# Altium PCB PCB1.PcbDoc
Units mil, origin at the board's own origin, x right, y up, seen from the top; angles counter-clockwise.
Board outline 1987 x 1197 mil, 2 copper layers (Top Layer, Bottom Layer); 31 components, 16 nets, 76 pads, 0 vias.
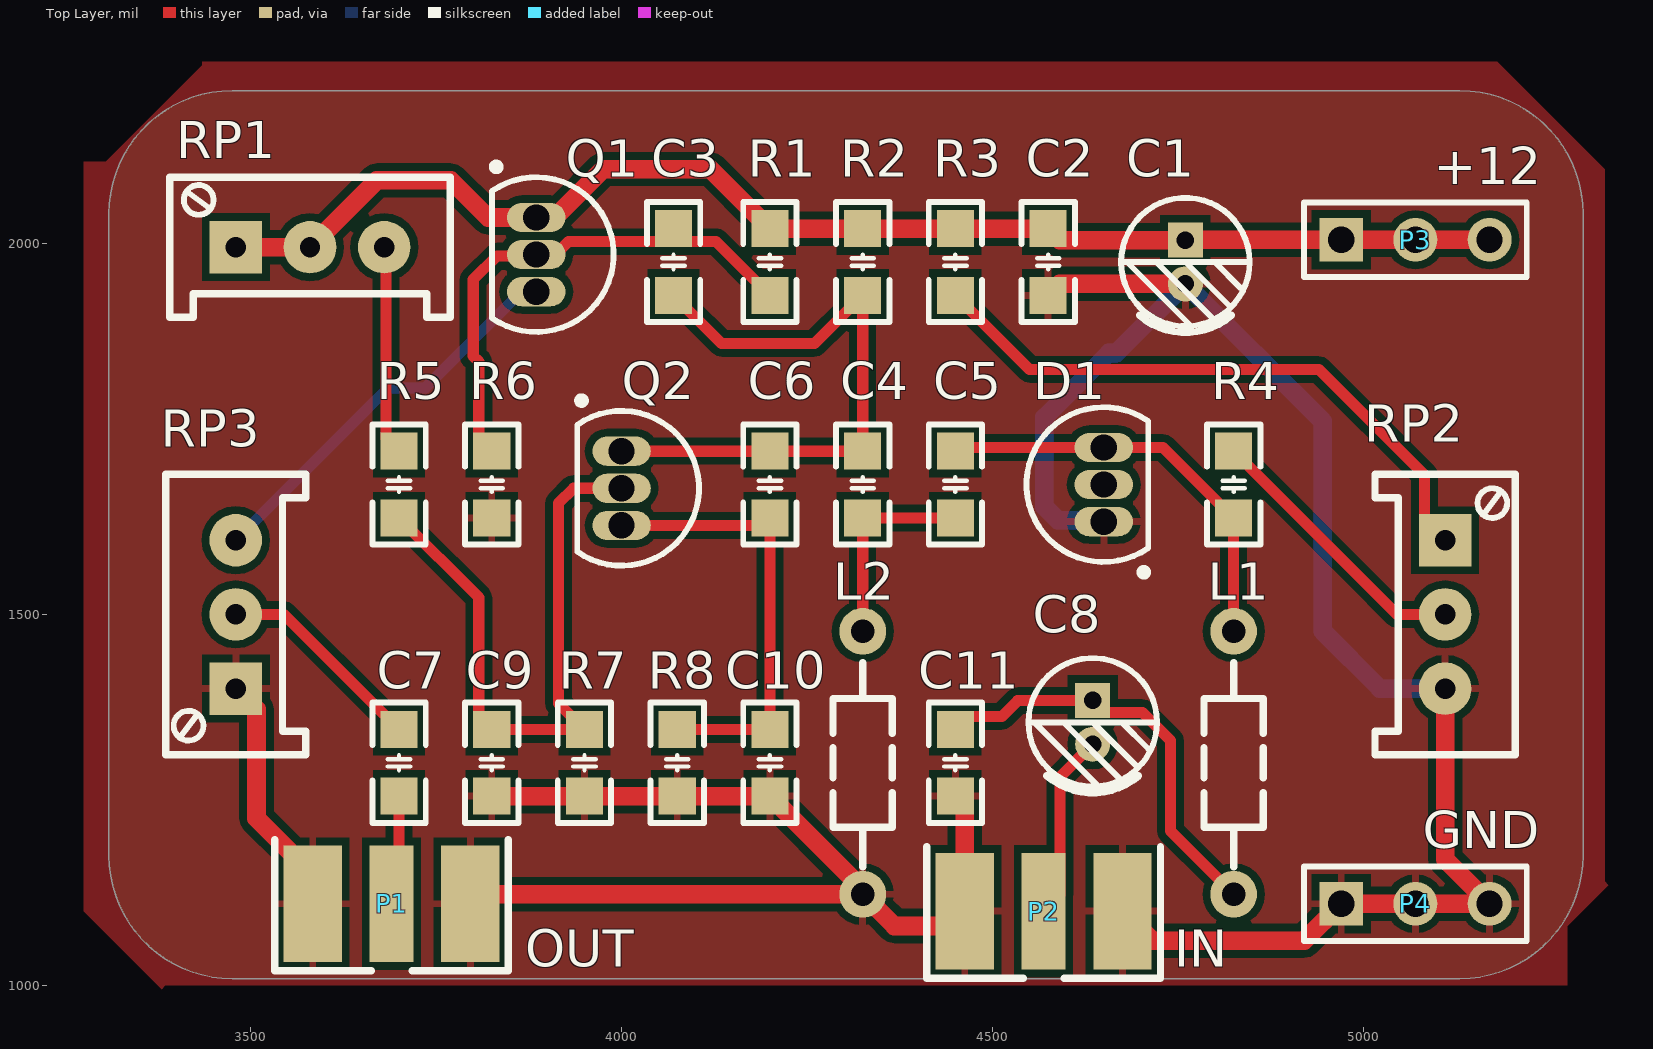
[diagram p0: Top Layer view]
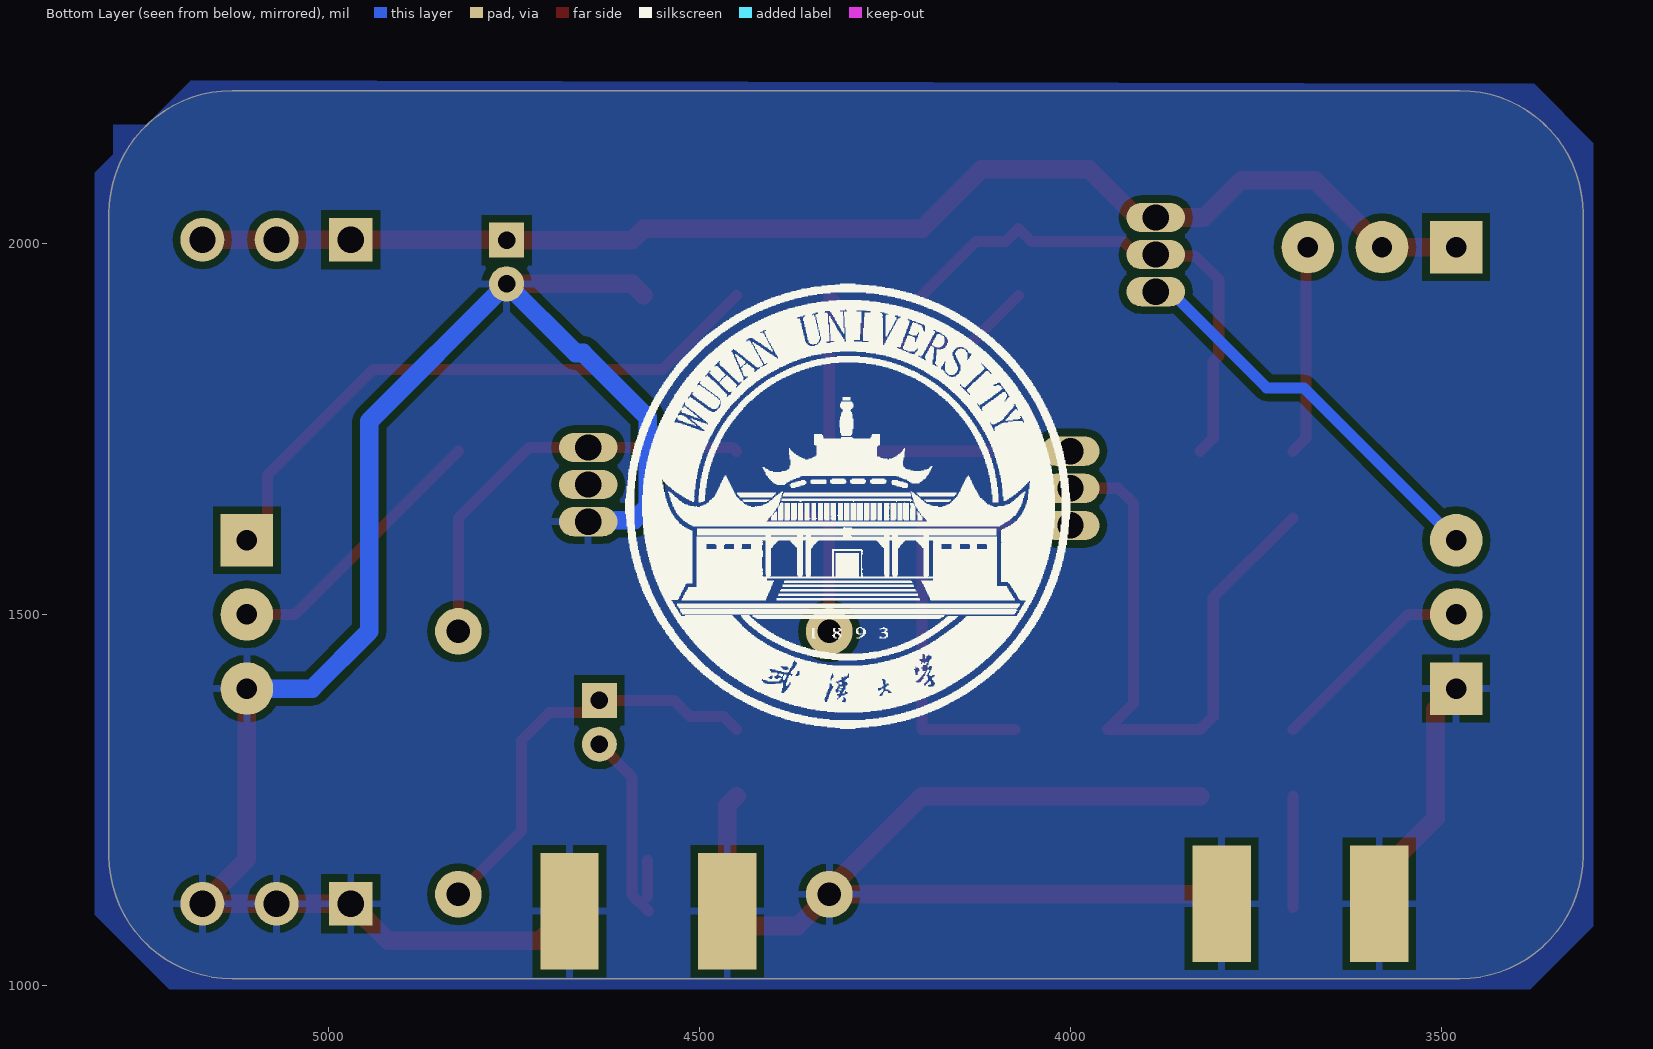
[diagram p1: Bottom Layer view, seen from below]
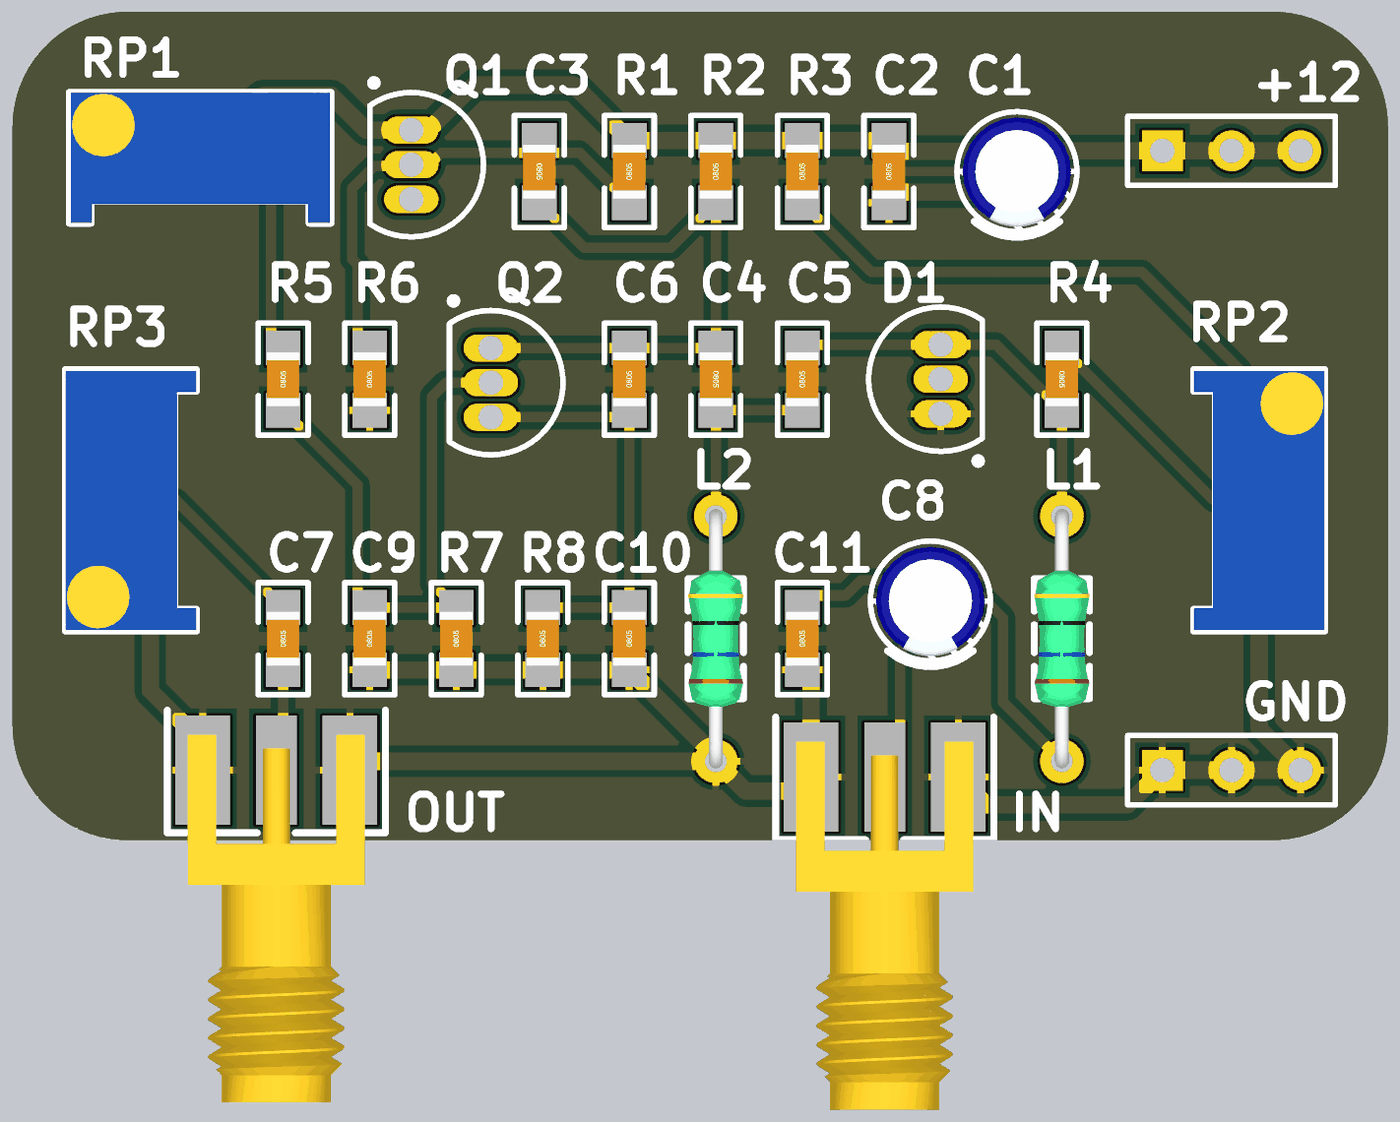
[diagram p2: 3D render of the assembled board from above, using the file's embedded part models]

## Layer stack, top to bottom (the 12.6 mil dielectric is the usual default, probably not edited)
Top Solder: solder mask 0.4, Solder Resist, Dk 3.5
Top Layer: signal copper 1.4
Dielectric 1: dielectric 12.6, FR-4, Dk 4.8
Bottom Layer: signal copper 1.4
Bottom Solder: solder mask 0.4, Solder Resist, Dk 3.5

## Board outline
3309,1175 ccw(c3475,1175) 3475,1009 5130,1009 ccw(c5130,1175) 5296,1175 5296,2040 ccw(c5130,2040) 5130,2206 3475,2206 ccw(c3475,2040) 3309,2040

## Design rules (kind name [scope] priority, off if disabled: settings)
Clearance [All] p1: gap=10 ignorepadtopadclearanceinfootprint=FALSE except(0: Arc-Hole Track-Hole SMDPad-Hole THPad-Hole Via-Hole Fill-Hole Poly-Hole Region-Hole Text-Hole; 1: Arc-Text Track-Text SMDPad-Text THPad-Text Via-Text Fill-Text Poly-Text Region-Text)
MinimumSolderMaskSliver [All] p1: minsoldermaskwidth=1
PolygonConnect [All] p1: connectstyle=Relief reliefconductorwidth=10 reliefentries=4 polygonreliefangle="90 Angle" airgapwidth=10
RoutingVias [All] p1: holewidth=28 width=50 viastyle="Through Hole" minholewidth=28 minwidth=50 maxholewidth=28 maxwidth=50
SilkToSilkClearance [All] p1: silktosilkclearance=1
SilkToSolderMaskClearance [IsPad] p1: minsilkscreentomaskgap=0 clearancetoexposedcopper=TRUE
SolderMaskExpansion [All] p1: expansion=4
Width [All] p1: maxlimit=50 minlimit=10 preferedwidth=15 minimp=50.000000 maximp=50.000000 favimp=50.000000
27 further rules are at their usual default settings.

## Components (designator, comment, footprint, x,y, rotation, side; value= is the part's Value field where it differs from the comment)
C1 "Cap Pol1" "CAP 1.5*4*8" 4760,1975 r270 top value=10uF
C2 "Cap" "C 0805_M" 4575,1975 r90 top value=10nF
C3 "Cap" "C 0805_M" 4070,1975 r270 top value=10pF
C4 "Cap" "C 0805_M" 4325,1675 r270 top value=51pF
C5 "Cap" "C 0805_M" 4450,1675 r90 top value=100nF
C6 "Cap" "C 0805_M" 4200,1675 r90 top value=300pF
C7 "Cap" "C 0805_M" 3700,1300 r90 top value=100pF
C8 "Cap Pol1" "CAP 1.5*4*8" 4635,1354.53 r270 top value=10uF
C9 "Cap" "C 0805_M" 3825,1300 r90 top value=10nF
C10 "Cap" "C 0805_M" 4200,1300 r90 top value=1nF
C11 "Cap" "C 0805_M" 4450,1300 r90 top value=1nF
D1 "BB910" TO-226-AA 4650,1675 r0 top
L1 "Inductor" AL0204 4825,1300 r90 top value=100uH
L2 "Inductor" AL0204 4325,1300 r90 top value=4.7uH
P1 "OUT" SMA-KE 3690,1110 r180 top
P2 "IN" SMA-KE 4568.9,1100 r180 top
P3 "+12" HDR1X3 4970,2005 r0 top
P4 "GND" HDR1X3 4970,1110 r0 top
Q1 "NPN" TO-226-AA 3885,1985 r180 top
Q2 "NPN" TO-226-AA 4000,1670 r180 top
R1 "Res1" "C 0805_M" 4200,1975 r90 top value=56K
R2 "Res1" "C 0805_M" 4325,1975 r90 top value=2K
R3 "Res1" "C 0805_M" 4450,1975 r90 top value=10K
R4 "Res1" "C 0805_M" 4825,1675 r270 top value=200K
R5 "Res1" "C 0805_M" 3700,1675 r90 top value=33K
R6 "Res1" "C 0805_M" 3825,1675 r90 top value=20K
R7 "Res1" "C 0805_M" 3950,1300 r90 top value=20K
R8 "Res1" "C 0805_M" 4075,1300 r90 top value=1K
RP1 "100K" 3296W 3580,1995 r0 top
RP2 "50K" 3296W 5110,1500 r270 top
RP3 "5K" 3296W 3480,1500 r90 top

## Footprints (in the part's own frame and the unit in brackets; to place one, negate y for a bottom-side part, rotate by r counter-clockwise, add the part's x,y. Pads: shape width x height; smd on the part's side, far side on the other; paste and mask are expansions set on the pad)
3296W [mm] "Precise Multi-Winding Adjustable Resistor"
  rect 1.8x1.8 hole 0.7: 1(-2.54,0)
  round 1.8 hole 0.7: 2(0,0) 3(2.54,0)
  silkscreen extent -4.8,-2.4 4.8,2.4, body extent -4.75,-2.4 4.75,2.4, height 11.52
AL0204 [mm] "9*2*4mm（脚距，直径，长度）"
  round 1.6 hole 0.8: 1(-4.5,0) 2(4.5,0)
  silkscreen extent -3.56,-1.02 3.43,1.02, body extent -4.75,-1.02 4.75,1.02, height 2.07
"C 0805_M" [mil] "无极性贴片电容"
  rect 50x50 smd: 1(-45,0) 2(45,0)
  silkscreen extent -81,-36 81,36, body extent -39,-24 39,24, height 20
"CAP 1.5*4*8" [mm] "脚距1.5mm直径4mm高度8mm"
  rect 1.2x1.2 hole 0.6: 1(-0.75,0)
  round 1.2 hole 0.6: 2(0.75,0)
  silkscreen extent -2.2,-2.2 2.41,2.2, body extent -2,-2 2.02,2, height 8.04
HDR1X3 [mm] "Connector; Header; 3 Position"
  rect 1.5x1.5 hole 0.9: 1(0,0)
  round 1.5 hole 0.9: 2(2.54,0) 3(5.08,0)
  silkscreen extent -1.27,-1.27 6.35,1.27
SMA-KE [mm] "SMA 偏脚射频天线座"
  rect 1.5x4 smd: 1(0,0)
  rect 2x4 smd: 2(-2.7,0) 2(2.7,0)
  rect 2x4 smd far side: 3(-2.7,0) 3(2.7,0)
  silkscreen extent -4,-2.2 4,2.3, body extent -3.25,-1.3 3.25,12.2, height 3.75
TO-226-AA [mm] "TO, Flat Index; 3 In-Line, Axial Leads; Body Dia. 4.8mm; Leads 0.55 x 0.51 mm (max)"
  oval 2x1 hole 0.9: 1(0,-1.27) 2(0,0) 3(0,1.27)
  silkscreen extent -2.65,-3.13 1.52,2.65, body extent -2.65,-2.66 1.52,2.66, height 5.33

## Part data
C1 C8: "Polarized Capacitor (Radial)"
C2 C3 C4 C5 C6 C7 C9 C10 C11: "Capacitor"
D1: library part Diode, "Default Diode"
P1 P2: library part SMA, "SMA-2.4G射频天线接口"
P3 P4: library part "Header 3", "Header, 3-Pin"
Q1 Q2: "NPN Bipolar Transistor"
R1 R2 R3 R4 R5 R6 R7 R8: "Resistor"
RP1 RP2 RP3: library part RP-ID, "插件单联电位器"

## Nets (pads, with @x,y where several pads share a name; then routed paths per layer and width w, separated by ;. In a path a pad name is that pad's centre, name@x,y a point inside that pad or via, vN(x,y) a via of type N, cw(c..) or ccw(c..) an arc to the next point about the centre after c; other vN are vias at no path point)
+12: C1.1 C2.2 P3.1 P3.2 P3.3 Q1.1 R1.2 R2.2 R3.2 RP1.1 RP1.2 | length 1814.7
  Top Layer w25: RP1.1 RP1.2 3670,2085 3770,2085 3820,2035 Q1.1 3910,2035 3975,2100 4120,2100 R1.2 R2.2 R3.2 C2.2 4590.47,2004.53 4750,2004.53 4750.47,2005 P3.1 P3.2 P3.3
GND: C1.2 C2.1 C9.1 C10.1 C11.1 D1.1 L2.1 P1.2 P1.3 P2.2 P2.3 P4.1 P4.2 P4.3 R6.1 R7.1 R8.1 RP2.3 RP3.1 | length 3937.6
  Top Layer w15: P1.2@3580,1110 P1.2@3583.7,1110 ; P1.2@3806.3,1105 P1.2@3824.13,1122.83 ; L2.1 L2.1@4325,1130
  Top Layer w25: RP3.1 3507.93,1372.07 3507.93,1225.14 P1.2@3568.07,1165 ; P1.2@3824.13,1122.83 L2.1 4367.83,1080 4442.6,1080 4462.6,1100 4462.6,1242.4 C11.1 ; C9.1 R7.1 R8.1 C10.1 L2.1@4325,1130 ; C2.1 4590.47,1945.47 C1.2 ; P2.2@4675.2,1100 4715.2,1060 4920,1060 P4.1 P4.2 P4.3 5110,1170 RP2.3
  Bottom Layer w25: D1.1 4648.13,1626.87 4588.13,1626.87 4570,1645 4570,1765.47 4656.92,1852.39 4666.92,1852.39 C1.2 4945,1760.47 4945,1477.17 5022.17,1400 RP2.3
NetC3_1: C3.1 Q1.2 R1.1 R6.2 | length 707.3
  Top Layer w15: R6.2 3807.5,1737.5 3807.5,1840.61 3800,1848.11 3800,1951.21 3831.92,1983.13 3883.13,1983.13 Q1.2 3911.28,1985 3928.78,2002.5 4052.5,2002.5 C3.1 4087.5,2002.5 4127.5,2002.5 R1.1
NetC3_2: C3.2 C4.1 C6.2 Q2.1 R2.1 | length 843.8
  Top Layer w15: Q2.1 C6.2 C4.1 R2.1 4260,1865 4135,1865 C3.2
NetC4_2: C4.2 C5.1 L2.2 | length 277.8
  Top Layer w15: L2.2 C4.2 C5.1
NetC5_2: C5.2 D1.3 L1.2 R4.2 | length 569.3
  Top Layer w15: C5.2 4455,1725 D1.3 4730,1725 R4.2 L1.2
NetC6_1: C6.1 C10.2 Q2.3 R8.2 | length 614.1
  Top Layer w15: Q2.3 4190,1620 C6.1 C10.2 R8.2
NetC7_1: C7.1 P1.1 | length 150
  Top Layer w15: P1.1@3700,1105 C7.1
NetC7_2: C7.2 RP3.2 | length 284.2
  Top Layer w15: RP3.2 3545,1500 C7.2
NetC8_1: C8.1 C11.2 L1.1 | length 570.9
  Top Layer w15: C11.2 4467.5,1362.5 4512.5,1362.5 4534.06,1384.06 C8.1 4651.12,1367.93 4702.07,1367.93 4740,1330 4740,1207.83 L1.1
NetC8_2: C8.2 P2.1 | length 301.6
  Top Layer w15: P2.1 4590.93,1122.03 4590.93,1280.93 C8.2 ; P2.1@4570.2,1120 P2.1@4570.2,1169.21
NetC9_2: C9.2 Q2.2 R5.1 R7.2 | length 874.6
  Top Layer w15: R5.1 3807.5,1522.5 3807.5,1362.5 C9.2 R7.2 3915,1380 3915,1650 3935,1670 Q2.2
NetQ1_3: Q1.3 RP3.3 | length 546.9
  Bottom Layer w15: RP3.3 3685,1805 3735.32,1805 3860,1929.68 3860,1935 Q1.3
NetR3_1: R3.1 RP2.1 | length 831.8
  Top Layer w15: R3.1 4550,1830 4940,1830 5082.07,1687.93 5082.07,1627.93 RP2.1
NetR4_1: R4.1 RP2.2 | length 376.1
  Top Layer w15: R4.1 4990,1555 5045,1500 RP2.2
NetR5_2: R5.2 RP1.3 | length 283.3
  Top Layer w15: RP1.3 3682.5,1992.5 3682.5,1737.5 R5.2
pads on no net: D1.2

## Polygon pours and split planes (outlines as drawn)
GND on Top Layer (solid, pour order 0): 3435,2240 3305,2110 3275,2110 3275,1100 3380,995 3385,1000 5275,1000 5275,1080 5330,1135 5325,1140 5325,2100 5180,2245 3435,2245
GND on Bottom Layer (solid, pour order 2): 3435,2215 3375,2215 3295,2135 3295,1080 3380,995 5215,995 5315,1095 5315,2095 5290,2120 5290,2160 5245,2160 5185,2220

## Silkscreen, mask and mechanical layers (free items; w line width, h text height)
Bottom Overlay:
  drawing of 5882 lines, arcs and shapes, not listed
Mechanical 1:
  lines w3.94: 3309,1175 ccw(c3475,1175) 3475,1009 3923.75,1009 4681.25,1009 5130,1009 ccw(c5130,1175) 5296,1175 5296,2040 ccw(c5130,2040) 5130,2206 3475,2206 ccw(c3475,2040) 3309,2040 3309,1950 3309,1175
